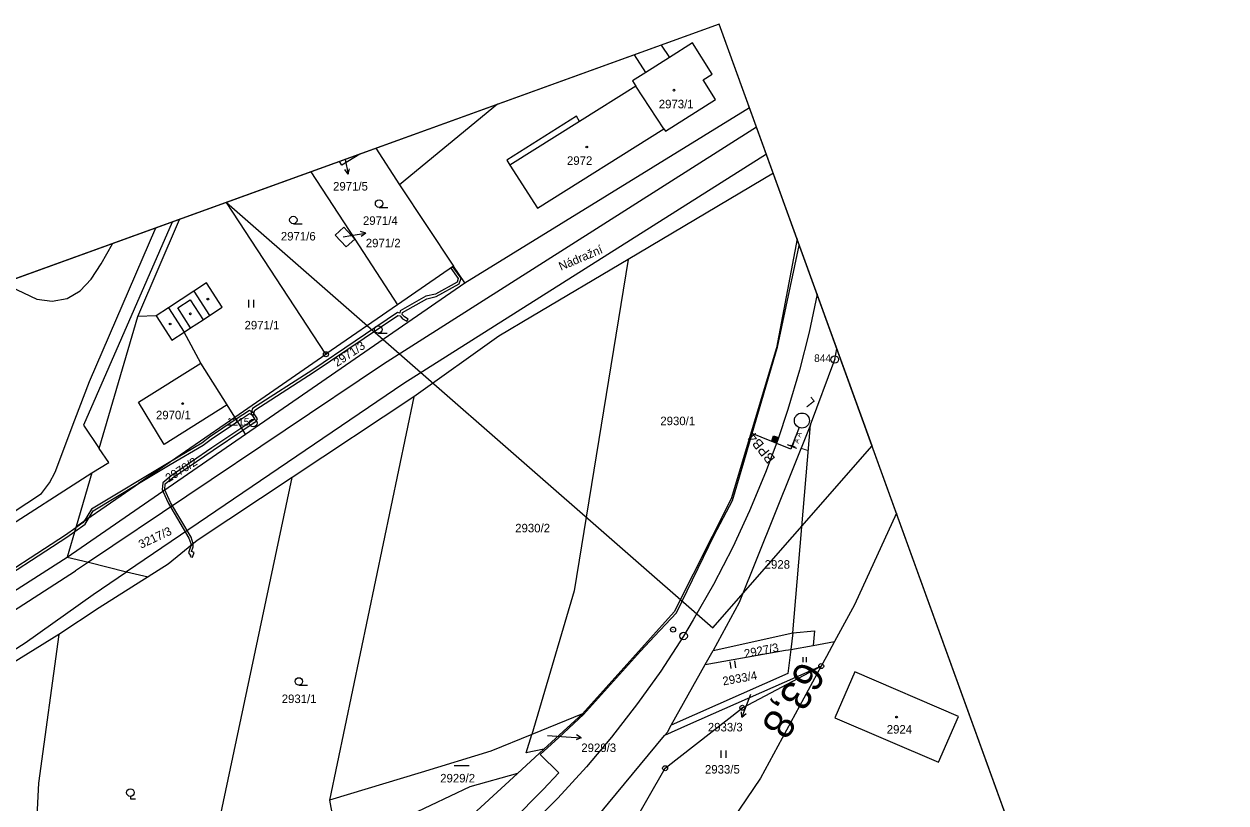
# Model space of a CAD drawing. Extents: x -620552 to -620056, y -1123312 to -1122890.
# Drawn here: x -620295.9 to -620056.1, y -1123045.1 to -1122889.6 of the extents above; entities that cross this region are included whole.
import ezdxf

# ---------------------------------------------------------------- set-up
doc = ezdxf.new("R2010")
doc.units = 0
for name, color, linetype in [('HranDP', 7, 'Continuous'), ('Hranice parcel', 7, 'Continuous'), ('Parcelní čísla', 7, 'Continuous'), ('Pop  PČ popisy', 7, 'Continuous'), ('Rámečky', 7, 'Continuous'), ('Rámečky-tisk', 7, 'Continuous'), ('Vnitřní kresba', 7, 'Continuous'), ('Vrstva 1', 7, 'Continuous'), ('Vrstva 2', 7, 'Continuous'), ('Vrstva 3', 7, 'Continuous'), ('Vrstva 6', 7, 'Continuous'), ('Vrstva 7', 7, 'Continuous'), ('Věcná břemena k části', 7, 'Continuous'), ('Značky bodu BP', 7, 'Continuous'), ('Značky budov', 7, 'Continuous'), ('Značky kultur', 7, 'Continuous')]:
    doc.layers.add(name, color=color, linetype=linetype)

msp = doc.modelspace()

# ---------------------------------------------------------------- linework, layer by layer
at = {"layer": 'HranDP'}
for p, q in [((-620160.04, -1123017.49), (-620158.39, -1123014.71)), ((-620166.78, -1123029.59), (-620160.04, -1123017.49)), ((-620184.51, -1123027.31), (-620192.2, -1123034.39)), ((-620192.2, -1123034.39), (-620197.49, -1123039.27))]:
    msp.add_line(p, q, dxfattribs=at)
for points in [[(-620141.66, -1122932.48), (-620145.74, -1122954.29), (-620154.8, -1122984.44), (-620166.17, -1123006.98), (-620184.51, -1123027.31)], [(-620139.01, -1122969.61), (-620134.15, -1122956.58), (-620133.7, -1122954.48)], [(-620139.01, -1122969.61), (-620153.24, -1123005.09), (-620158.39, -1123014.71)], [(-620168.12, -1123031.65), (-620167.55, -1123030.97), (-620166.78, -1123029.59)], [(-620243.96, -1123098.03), (-620228.02, -1123087.3), (-620208.81, -1123075.27), (-620182.41, -1123048.95), (-620179.31, -1123045.19), (-620168.12, -1123031.65)], [(-620197.49, -1123039.27), (-620212.08, -1123052.71), (-620231.41, -1123063.68)]]:
    msp.add_lwpolyline(points, dxfattribs=at)
at = {"layer": 'Hranice parcel'}
for p, q in [((-620208, -1122941.31), (-620151.16, -1122906.27)), ((-620225.71, -1122914.41), (-620220.99, -1122921.7)), ((-620146.4, -1122919.39), (-620175.35, -1122936.6)), ((-620220.99, -1122921.7), (-620210.21, -1122937.96)), ((-620235.69, -1122955.55), (-620255.53, -1122925.21)), ((-620273.22, -1122947.97), (-620264.92, -1122928.61)), ((-620210.21, -1122937.96), (-620221.39, -1122945.68)), ((-620208, -1122941.31), (-620210.21, -1122937.96)), ((-620251.74, -1122971.48), (-620208, -1122941.31)), ((-620221.39, -1122945.68), (-620235.69, -1122955.55)), ((-620201.16, -1122951.94), (-620218.17, -1122964.05)), ((-620253.87, -1122968.1), (-620235.69, -1122955.55)), ((-620218.17, -1122964.05), (-620242.46, -1122980.18)), ((-620218.17, -1122964.05), (-620234.98, -1123044.6)), ((-620285.54, -1122989.95), (-620253.87, -1122968.1)), ((-620251.74, -1122971.48), (-620253.87, -1122968.1)), ((-620287.33, -1122996.04), (-620251.74, -1122971.48)), ((-620142.51, -1123011.15), (-620139.01, -1122969.61)), ((-620369, -1123034.76), (-620282.4, -1122979.23)), ((-620282.4, -1122979.23), (-620285.54, -1122989.95)), ((-620263.28, -1123078.74), (-620242.46, -1122980.18)), ((-620285.54, -1122989.95), (-620287.33, -1122996.04)), ((-620280.96, -1123006.18), (-620289.02, -1123011.5)), ((-620289.02, -1123011.5), (-620330.98, -1123037.45)), ((-620158.39, -1123014.71), (-620142.51, -1123011.15)), ((-620142.51, -1123011.15), (-620142.91, -1123014.47)), ((-620160.04, -1123017.49), (-620158.39, -1123014.71)), ((-620142.91, -1123014.47), (-620138.43, -1123013.68)), ((-620138.43, -1123013.68), (-620134.2, -1123012.93)), ((-620166.78, -1123029.59), (-620160.04, -1123017.49)), ((-620152.59, -1123026.13), (-620136.85, -1123017.81)), ((-620136.85, -1123017.81), (-620148.96, -1123040.16)), ((-620184.51, -1123027.31), (-620194.62, -1123031.45)), ((-620184.51, -1123027.31), (-620192.2, -1123034.39)), ((-620192.2, -1123034.39), (-620197.49, -1123039.27)), ((-620148.96, -1123040.16), (-620158.39, -1123054.01)), ((-620234.98, -1123044.6), (-620234.38, -1123047.81))]:
    msp.add_line(p, q, dxfattribs=at)
for points in [[(-620168.81, -1122893.81), (-620167.12, -1122896.26), (-620171.85, -1122899.25), (-620174.08, -1122895.72)], [(-620198.98, -1122917.79), (-620193.45, -1122926.35), (-620168.27, -1122910.5), (-620173.85, -1122901.99), (-620185.06, -1122909.04), (-620185.7, -1122908.03), (-620199.62, -1122916.78), (-620198.98, -1122917.79)], [(-620201.44, -1122905.62), (-620220.99, -1122921.7)], [(-620228.95, -1122915.59), (-620232.52, -1122917.77), (-620232.97, -1122917.04)], [(-620238.74, -1122919.13), (-620229.95, -1122932.57), (-620221.39, -1122945.68)], [(-620229.95, -1122932.57), (-620232.13, -1122930.14), (-620233.86, -1122931.77)], [(-620233.86, -1122931.77), (-620231.67, -1122934.08), (-620229.95, -1122932.57)], [(-620141.66, -1122932.48), (-620145.74, -1122954.29), (-620154.8, -1122984.44), (-620166.17, -1123006.98), (-620184.51, -1123027.31)], [(-620175.35, -1122936.6), (-620194.44, -1122947.94), (-620201.16, -1122951.94)], [(-620175.35, -1122936.6), (-620186.12, -1123002.76), (-620194.62, -1123031.45)], [(-620253.87, -1122968.1), (-620255.41, -1122965.65), (-620260.66, -1122957.29), (-620263.97, -1122951.11), (-620262.72, -1122950.29), (-620260.22, -1122948.64), (-620258.93, -1122947.79), (-620256.43, -1122946.15), (-620259.56, -1122941.28), (-620262.06, -1122942.93), (-620267.1, -1122946.24), (-620269.6, -1122947.89), (-620273.22, -1122947.97)], [(-620282.4, -1122979.23), (-620279.03, -1122977.17), (-620280.97, -1122974.36), (-620273.22, -1122947.97)], [(-620139.01, -1122969.61), (-620134.15, -1122956.58), (-620133.7, -1122954.48)], [(-620139.01, -1122969.61), (-620153.24, -1123005.09), (-620158.39, -1123014.71)], [(-620242.46, -1122980.18), (-620261.36, -1122992.76), (-620267.21, -1122997.48)], [(-620121.82, -1122987.28), (-620130.2, -1123005.56), (-620134.2, -1123012.93)], [(-620365.22, -1123044.99), (-620354.45, -1123039), (-620287.33, -1122996.04)], [(-620267.21, -1122997.48), (-620271.2, -1123000), (-620280.96, -1123006.18)], [(-620289.02, -1123011.5), (-620293.05, -1123041.17), (-620295.61, -1123091.1), (-620294.3, -1123096.22)], [(-620142.91, -1123014.47), (-620143.48, -1123019.27), (-620166.78, -1123029.59)], [(-620160.04, -1123017.49), (-620143.96, -1123014.65), (-620143.4, -1123014.55), (-620142.91, -1123014.47)], [(-620134.2, -1123012.93), (-620135.79, -1123015.87), (-620136.85, -1123017.81)], [(-620136.85, -1123017.81), (-620163.54, -1123029.62), (-620168.12, -1123031.65)], [(-620134.13, -1123028.15), (-620113.42, -1123037.02), (-620109.47, -1123027.84), (-620130.15, -1123018.97), (-620134.13, -1123028.15)], [(-620169.42, -1123054.19), (-620174.5, -1123049.57), (-620168, -1123038.2), (-620152.59, -1123026.13)], [(-620194.62, -1123031.45), (-620202.81, -1123034.81), (-620216.72, -1123039.04), (-620234.98, -1123044.6)], [(-620192.2, -1123034.39), (-620195.73, -1123035.14), (-620194.62, -1123031.45)], [(-620168.12, -1123031.65), (-620167.55, -1123030.97), (-620166.78, -1123029.59)], [(-620243.96, -1123098.03), (-620228.02, -1123087.3), (-620208.81, -1123075.27), (-620182.41, -1123048.95), (-620179.31, -1123045.19), (-620168.12, -1123031.65)], [(-620197.49, -1123039.27), (-620207, -1123041.9), (-620218.72, -1123047.54), (-620234.38, -1123047.81)], [(-620197.49, -1123039.27), (-620212.08, -1123052.71), (-620231.41, -1123063.68)]]:
    msp.add_lwpolyline(points, dxfattribs=at)
at = {"layer": 'Pop  PČ popisy'}
for p, q in [((-620231.26, -1122919.57), (-620231.94, -1122918.68)), ((-620231.83, -1122916.63), (-620231.26, -1122919.57)), ((-620231.26, -1122919.57), (-620230.96, -1122918.49)), ((-620232.28, -1122932.09), (-620230.7, -1122931.83)), ((-620230.7, -1122931.83), (-620227.74, -1122931.36)), ((-620227.74, -1122931.36), (-620228.8, -1122931.02)), ((-620227.74, -1122931.36), (-620228.65, -1122932.01)), ((-620150.94, -1123023.48), (-620151.6, -1123025.22)), ((-620151.6, -1123025.22), (-620152.68, -1123028.02)), ((-620152.68, -1123028.02), (-620152.78, -1123026.91)), ((-620152.68, -1123028.02), (-620151.85, -1123027.27)), ((-620191.47, -1123031.65), (-620187.72, -1123031.92)), ((-620187.72, -1123031.92), (-620184.73, -1123032.13)), ((-620184.73, -1123032.13), (-620185.76, -1123032.56)), ((-620184.73, -1123032.13), (-620185.69, -1123031.56))]:
    msp.add_line(p, q, dxfattribs=at)
at = {"layer": 'Rámečky'}
for p, q in [((-620157.19, -1122889.6), (-620552.1, -1123032.6)), ((-620056.07, -1123168.86), (-620157.19, -1122889.6))]:
    msp.add_line(p, q, dxfattribs=at)
for points in [[(-620126.7, -1122973.8), (-620157.19, -1122889.6), (-620255.57, -1122925.22)], [(-620255.57, -1122925.22), (-620158.49, -1123010.14), (-620126.7, -1122973.8)]]:
    msp.add_lwpolyline(points, dxfattribs=at)
at = {"layer": 'Rámečky-tisk'}
for points in [[(-620450.98, -1123311.85), (-620056.07, -1123168.86), (-620157.19, -1122889.6), (-620552.1, -1123032.6)], [(-620126.7, -1122973.8), (-620157.19, -1122889.6), (-620255.57, -1122925.22)], [(-620255.57, -1122925.22), (-620158.49, -1123010.14), (-620126.7, -1122973.8)]]:
    msp.add_lwpolyline(points, dxfattribs=at)
at = {"layer": 'Vnitřní kresba'}
for p, q in [((-620162.51, -1122893.37), (-620167.12, -1122896.26)), ((-620158.59, -1122899.61), (-620162.51, -1122893.37)), ((-620171.85, -1122899.25), (-620174.52, -1122900.92)), ((-620174.52, -1122900.92), (-620173.85, -1122901.99)), ((-620160.44, -1122900.76), (-620158.59, -1122899.61)), ((-620157.94, -1122904.69), (-620160.44, -1122900.76)), ((-620167.95, -1122911), (-620157.94, -1122904.69)), ((-620185.06, -1122909.04), (-620198.98, -1122917.79)), ((-620149.74, -1122910.17), (-620224.19, -1122957.54)), ((-620168.27, -1122910.5), (-620167.95, -1122911)), ((-620147.79, -1122915.57), (-620220.18, -1122961.38)), ((-620266.41, -1122929.15), (-620284.09, -1122969.72)), ((-620282.88, -1122960.95), (-620269.65, -1122930.32)), ((-620280.53, -1122937.51), (-620278.32, -1122933.46)), ((-620282.53, -1122940.57), (-620280.53, -1122937.51)), ((-620300.01, -1122941.39), (-620293.37, -1122944.55)), ((-620284.77, -1122942.9), (-620282.53, -1122940.57)), ((-620293.37, -1122944.55), (-620290.35, -1122944.97)), ((-620290.35, -1122944.97), (-620287.32, -1122944.4)), ((-620287.32, -1122944.4), (-620284.77, -1122942.9)), ((-620265.27, -1122946.29), (-620262.76, -1122944.66)), ((-620262.76, -1122944.66), (-620260.22, -1122948.64)), ((-620262.06, -1122942.93), (-620258.93, -1122947.79)), ((-620267.1, -1122946.24), (-620263.97, -1122951.11)), ((-620262.72, -1122950.29), (-620265.27, -1122946.29)), ((-620269.6, -1122947.89), (-620266.47, -1122952.75)), ((-620266.47, -1122952.75), (-620263.97, -1122951.11)), ((-620224.19, -1122957.54), (-620283.1, -1122997.08)), ((-620273.13, -1122965.13), (-620260.66, -1122957.29)), ((-620285.84, -1122968.66), (-620282.88, -1122960.95)), ((-620220.18, -1122961.38), (-620275.49, -1122998.97)), ((-620267.97, -1122973.56), (-620273.13, -1122965.13)), ((-620255.41, -1122965.65), (-620267.97, -1122973.56)), ((-620289.73, -1122979.06), (-620285.84, -1122968.66)), ((-620284.09, -1122969.72), (-620280.97, -1122974.36)), ((-620290.87, -1122981.21), (-620289.73, -1122979.06)), ((-620307.51, -1122993.27), (-620292.44, -1122983.33)), ((-620292.44, -1122983.33), (-620290.87, -1122981.21)), ((-620287.33, -1122996.04), (-620283.1, -1122997.08)), ((-620283.1, -1122997.08), (-620285.65, -1122998.79)), ((-620283.1, -1122997.08), (-620275.49, -1122998.97)), ((-620336.04, -1123031.13), (-620285.65, -1122998.79)), ((-620282.13, -1123003.48), (-620275.49, -1122998.97)), ((-620275.49, -1122998.97), (-620271.2, -1123000)), ((-620295.72, -1123013.16), (-620282.13, -1123003.48)), ((-620142.51, -1123011.15), (-620138.18, -1123010.74)), ((-620138.18, -1123010.74), (-620138.43, -1123013.68)), ((-620339.98, -1123041.29), (-620295.72, -1123013.16))]:
    msp.add_line(p, q, dxfattribs=at)
at = {"layer": 'Vrstva 1'}
for p, q in [((-620148.83, -1122972.09), (-620150.63, -1122971.37)), ((-620142.94, -1122974.46), (-620148.83, -1122972.09)), ((-620142.71, -1122973.89), (-620142.94, -1122974.46))]:
    msp.add_line(p, q, dxfattribs=at)
for points in [[(-620150.63, -1122971.37), (-620145.98, -1122955.43), (-620145.54, -1122954.13), (-620141.24, -1122933.85), (-620141.21, -1122933.72)], [(-620137.67, -1122943.51), (-620139.25, -1122951.1), (-620141.18, -1122958.74), (-620143.49, -1122966.59), (-620145.52, -1122972.66), (-620147.96, -1122979.17), (-620151.13, -1122986.8), (-620154.5, -1122994.08), (-620158.35, -1123001.53), (-620162.37, -1123008.6), (-620164.31, -1123011.8), (-620168.88, -1123018.81), (-620173.5, -1123025.27), (-620178.73, -1123032.03), (-620183.71, -1123037.93), (-620189.42, -1123044.16), (-620195.41, -1123050.18)], [(-620302.99, -1123100.7), (-620292.4, -1123098.24), (-620281.7, -1123095.56), (-620261.93, -1123088.35), (-620253.64, -1123085.66), (-620236.13, -1123076.73), (-620225.47, -1123069.74), (-620216.19, -1123063.28), (-620205.15, -1123054.34), (-620198.59, -1123048.78), (-620192.32, -1123042.45), (-620189.21, -1123039.13), (-620192.93, -1123035.47), (-620189.24, -1123032.05), (-620184.32, -1123027.49), (-620172.92, -1123014.85), (-620170.12, -1123011.86), (-620165.72, -1123007.16), (-620158.18, -1122991.64), (-620154.53, -1122984.74), (-620154, -1122982.93), (-620152.3, -1122977.09), (-620150.63, -1122971.37)]]:
    msp.add_lwpolyline(points, dxfattribs=at)
at = {"layer": 'Vrstva 2'}
for p, q in [((-620141.25, -1122970.17), (-620142.71, -1122973.89)), ((-620146.62, -1122972.63), (-620146.51, -1122972.86)), ((-620146.56, -1122972.45), (-620146.34, -1122972.92)), ((-620146.5, -1122972.28), (-620146.16, -1122972.98)), ((-620146.44, -1122972.1), (-620145.99, -1122973.05)), ((-620146.38, -1122971.93), (-620145.81, -1122973.11)), ((-620146.28, -1122971.83), (-620145.68, -1122973.09)), ((-620146.1, -1122971.89), (-620145.61, -1122972.92)), ((-620145.93, -1122971.95), (-620145.55, -1122972.74)), ((-620145.75, -1122972.02), (-620145.49, -1122972.57)), ((-620145.58, -1122972.08), (-620145.43, -1122972.39)), ((-620145.4, -1122972.14), (-620145.37, -1122972.22)), ((-620143.65, -1122973.53), (-620141.78, -1122974.26))]:
    msp.add_line(p, q, dxfattribs=at)
msp.add_lwpolyline([(-620145.35, -1122972.16), (-620145.7, -1122973.15), (-620146.69, -1122972.8), (-620146.34, -1122971.81)], close=True, dxfattribs=at)
msp.add_lwpolyline([(-620145.35, -1122972.16), (-620145.7, -1122973.15), (-620146.69, -1122972.8), (-620146.34, -1122971.81)], close=True, dxfattribs=at)
msp.add_circle((-620140.7, -1122968.78), 1.5, dxfattribs=at)
at = {"layer": 'Vrstva 6'}
for p, q in [((-620143.06, -1122973.69), (-620142.12, -1122974)), ((-620141.96, -1122971.97), (-620142.59, -1122973.84))]:
    msp.add_line(p, q, dxfattribs=at)
at = {"layer": 'Vrstva 7'}
msp.add_line((-620166.39, -1123010.47), (-620166.44, -1123010.56), dxfattribs=at)
for centre, radius in [((-620166.42, -1123010.52), 0.5), ((-620164.31, -1123011.8), 0.75)]:
    msp.add_circle(centre, radius, dxfattribs=at)
at = {"layer": 'Věcná břemena k části'}
for points in [[(-620220.85, -1122947.88), (-620220.38, -1122948.48), (-620219.54, -1122948.96), (-620219.3, -1122948.52), (-620220.04, -1122948.1), (-620220.45, -1122947.58), (-620220.43, -1122947.18), (-620215.58, -1122944.45), (-620213.67, -1122944.01), (-620209.12, -1122941.46), (-620208.72, -1122940.34), (-620210.39, -1122938.08), (-620210.8, -1122938.37), (-620209.28, -1122940.42), (-620209.52, -1122941.12), (-620213.85, -1122943.53), (-620215.76, -1122943.97), (-620220.91, -1122946.88), (-620220.94, -1122947.35), (-620221.44, -1122947.23), (-620238.3, -1122958.63), (-620250.35, -1122966.38), (-620250.52, -1122967.01), (-620250.96, -1122966.76), (-620253.6, -1122968.53), (-620258.92, -1122972.11), (-620260.46, -1122973.29), (-620267, -1122977.16), (-620273.08, -1122981.36), (-620266.78, -1122977.55), (-620260.18, -1122973.71), (-620258.62, -1122972.51), (-620253.33, -1122968.95), (-620250.94, -1122967.34), (-620250.2, -1122967.75), (-620249.91, -1122966.7), (-620238.02, -1122959.05), (-620221.34, -1122947.77)], [(-620267.76, -1122981.44), (-620266.3, -1122980.23), (-620258.21, -1122974.67), (-620252.25, -1122970.68), (-620249.64, -1122968.93), (-620249.36, -1122968.41), (-620250.25, -1122967.05), (-620250.66, -1122967.34), (-620249.94, -1122968.43), (-620250.02, -1122968.59), (-620252.51, -1122970.26), (-620258.49, -1122974.25), (-620266.6, -1122979.83), (-620268.24, -1122981.19), (-620268.35, -1122982.6), (-620268.23, -1122982.86), (-620267.82, -1122982.58)], [(-620282.15, -1122986.83), (-620273.08, -1122981.36), (-620267, -1122977.16), (-620282.51, -1122986.47), (-620283.97, -1122988.87), (-620282.96, -1122988.17)], [(-620262.66, -1122993.81), (-620262.17, -1122993.41), (-620262.59, -1122992.04), (-620266.69, -1122985.11), (-620267.82, -1122982.58), (-620268.23, -1122982.86), (-620267.13, -1122985.33), (-620263.05, -1122992.26), (-620262.67, -1122993.31)], [(-620283.75, -1122989.47), (-620282.96, -1122988.17), (-620283.97, -1122988.87), (-620284.13, -1122989.13), (-620285.6, -1122990.17), (-620285.83, -1122990.94)], [(-620359.12, -1123037.46), (-620340.69, -1123026.08), (-620322.75, -1123014.93), (-620304.43, -1123003.11), (-620287.42, -1122992.06), (-620285.83, -1122990.94), (-620285.6, -1122990.17), (-620287.7, -1122991.64), (-620304.71, -1123002.69), (-620323.01, -1123014.51), (-620340.95, -1123025.66), (-620359.38, -1123037.04), (-620368.18, -1123042.28), (-620367.79, -1123042.63)], [(-620262.66, -1122993.81), (-620263.14, -1122995.17), (-620262.74, -1122995.71), (-620262.81, -1122995.9), (-620262.34, -1122996.07), (-620262, -1122995.13), (-620262.52, -1122994.94), (-620262.16, -1122994.01), (-620262.17, -1122993.41)]]:
    msp.add_lwpolyline(points, close=True, dxfattribs=at)
at = {"layer": 'Značky bodu BP'}
for centre, radius in [((-620235.69, -1122955.55), 0.5), ((-620235.69, -1122955.55), 0.0303), ((-620134.15, -1122956.58), 0.75), ((-620134.15, -1122956.58), 0.03), ((-620250.19, -1122969.27), 0.75), ((-620250.19, -1122969.27), 0.03), ((-620136.85, -1123017.81), 0.5), ((-620136.85, -1123017.81), 0.0303), ((-620152.59, -1123026.13), 0.5), ((-620152.59, -1123026.13), 0.0303), ((-620168, -1123038.2), 0.5), ((-620168, -1123038.2), 0.0303)]:
    msp.add_circle(centre, radius, dxfattribs=at)
at = {"layer": 'Značky budov'}
for centre in [(-620166.23, -1122902.81), (-620183.64, -1122914.16), (-620259.26, -1122944.53), (-620262.75, -1122947.47), (-620266.8, -1122949.49), (-620264.28, -1122965.39), (-620121.81, -1123027.99)]:
    msp.add_circle(centre, 0.175, dxfattribs=at)
at = {"layer": 'Značky kultur'}
for p, q in [((-620225.08, -1122926.21), (-620223.33, -1122926.21)), ((-620242.2, -1122929.48), (-620240.45, -1122929.48)), ((-620251.08, -1122946.18), (-620251.08, -1122944.68)), ((-620250.08, -1122946.18), (-620250.08, -1122944.68)), ((-620225.25, -1122951.34), (-620223.5, -1122951.34)), ((-620154.8, -1123018.32), (-620155.05, -1123016.94)), ((-620153.88, -1123018.16), (-620154.12, -1123016.77)), ((-620140.44, -1123017.02), (-620140.44, -1123016.02)), ((-620139.77, -1123017.02), (-620139.77, -1123016.02)), ((-620241.1, -1123021.62), (-620239.35, -1123021.62)), ((-620156.8, -1123036.14), (-620156.8, -1123034.64)), ((-620155.8, -1123036.14), (-620155.8, -1123034.64)), ((-620210.09, -1123037.67), (-620207.09, -1123037.67)), ((-620274.72, -1123043.82), (-620274.72, -1123044.32)), ((-620274.72, -1123044.32), (-620273.72, -1123044.32))]:
    msp.add_line(p, q, dxfattribs=at)
for centre in [(-620225.08, -1122925.46), (-620242.2, -1122928.73), (-620225.25, -1122950.59), (-620241.1, -1123020.87), (-620274.72, -1123043.07)]:
    msp.add_circle(centre, 0.75, dxfattribs=at)

# ---------------------------------------------------------------- texts
at = {"layer": 'Parcelní čísla'}
for s, p in [('2973/1', (-620169.27, -1122906.43)), ('2972', (-620187.59, -1122917.72)), ('2971/5', (-620234.27, -1122922.85)), ('2971/4', (-620228.31, -1122929.7)), ('2971/6', (-620244.69, -1122932.82)), ('2971/2', (-620227.74, -1122934.18)), ('2971/1', (-620251.94, -1122950.58)), ('2970/1', (-620269.62, -1122968.53)), ('2930/1', (-620168.96, -1122969.7)), ('2930/2', (-620197.92, -1122991.1)), ('2928', (-620148.13, -1122998.36)), ('2931/1', (-620244.52, -1123025.19)), ('2933/3', (-620159.47, -1123030.85)), ('2924', (-620123.77, -1123031.28)), ('2929/3', (-620184.73, -1123034.97)), ('2933/5', (-620160.05, -1123039.27)), ('2929/2', (-620212.89, -1123041.04))]:
    msp.add_text(s, height=1.7, dxfattribs=at).set_placement(p)
for s, rotation, p in [('2971/3', 34, (-620233.45, -1122958.11)), ('2970/2', 32, (-620267.08, -1122981.16)), ('3217/3', 25, (-620272.61, -1122994.39)), ('2927/3', 11, (-620152.05, -1123016.19)), ('2933/4', 10, (-620156.38, -1123021.67))]:
    msp.add_text(s, height=1.7, rotation=rotation, dxfattribs=at).set_placement(p)
at = {"layer": 'Pop  PČ popisy'}
msp.add_text('Nádražní', height=1.7, rotation=23, dxfattribs=at).set_placement((-620188.79, -1122938.87))
at = {"layer": 'Vrstva 3'}
for s, p in [('L', (-620137.97, -1122965.09)), ('BPB4', (-620145.92, -1122976.33))]:
    msp.add_text(s, height=2, rotation=128.542, dxfattribs=at).set_placement(p)
at = {"layer": 'Vrstva 6'}
for s, height, rotation, p in [('  A A ', 1, 71.5027, (-620141.64, -1122974.16)), ('L', 1.5, 251.5027, (-620140.85, -1122974.05))]:
    msp.add_text(s, height=height, rotation=rotation, dxfattribs=at).set_placement(p)
at = {"layer": 'Vrstva 7'}
msp.add_text('63,8', height=6, rotation=238.7026, dxfattribs=at).set_placement((-620140.84, -1123016.42))
at = {"layer": 'Značky bodu BP'}
for s, p in [('844', (-620138.25, -1122957.08)), ('1215', (-620255.44, -1122969.77))]:
    msp.add_text(s, height=1.5, dxfattribs=at).set_placement(p)

doc.saveas('drawing.dxf')
